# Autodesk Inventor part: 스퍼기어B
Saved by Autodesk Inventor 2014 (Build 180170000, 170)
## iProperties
Created: 2025-02
Part Number: 스퍼기어B
Material: 강철, 탄소
Document SubType Name: Modeling
Designer: dg
Density: 7.87 g/cm^3
Appearance: 반연마
Mass: 215.131 g
Surface Area: 92.0571 cm^2
Volume: 27.3355 cm^3
Author: jhkim
Creation Date: 2025-01-06
Sending System: Autodesk Inventor 2025
Preprocessor: ST-DEVELOPER v20
Author: dg
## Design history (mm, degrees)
node "스퍼기어B1"
node "솔리드1"
node "기준1"
